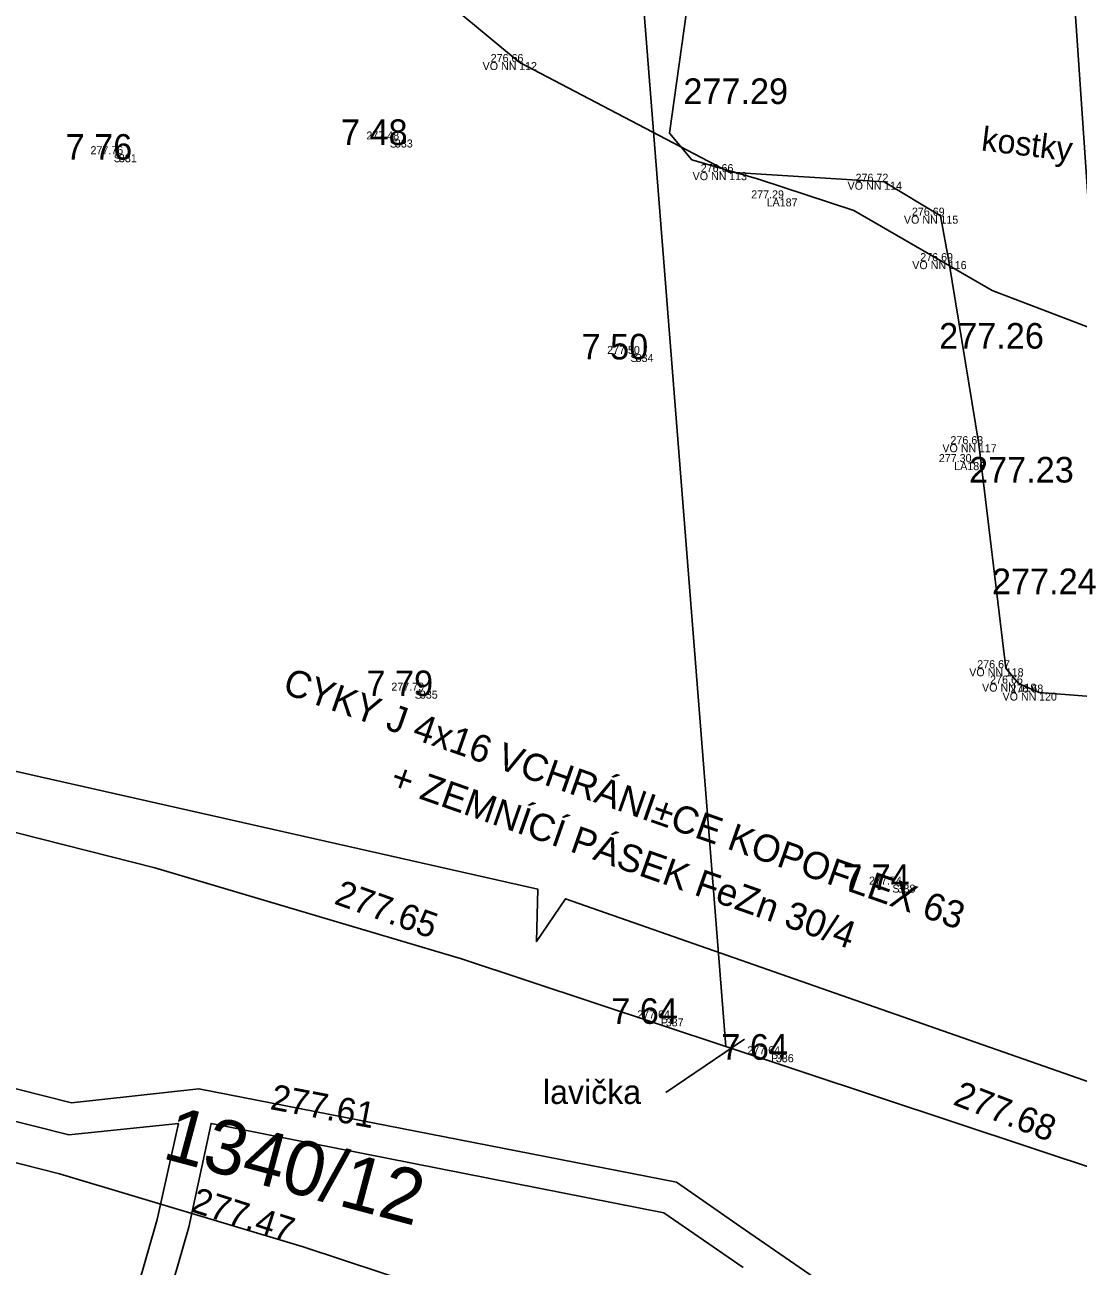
# Model space of a CAD drawing. Extents: x -601602 to -600882, y -1162594 to -1161950.
# Drawn here: x -601167.11 to -601150.66, y -1162089.58 to -1162070.19 of the extents above; entities that cross this region are included whole.
import ezdxf

# ---------------------------------------------------------------- set-up
doc = ezdxf.new("R2010")
doc.units = 0
for name, color, linetype in [('BODY', 7, 'Continuous'), ('BODY_CISLA', 7, 'Continuous'), ('BODY_KODY', 7, 'Continuous'), ('BODY_VYSKY_CELE', 7, 'Continuous'), ('G_TEXTY', 7, 'Continuous'), ('H_KOTY_VYSKOVE', 7, 'Continuous'), ('H_VYSKY_PREVZATE', 7, 'Continuous'), ('IS_EON_NN', 7, 'Continuous'), ('IS_VO', 7, 'Continuous'), ('IS_VO_AREAL', 7, 'Continuous'), ('KN_Hranice parcel', 7, 'Continuous'), ('KN_Parcelní čísla', 7, 'Continuous'), ('KN_Věcná břemena k části', 7, 'Continuous')]:
    doc.layers.add(name, color=color, linetype=linetype)

# ---------------------------------------------------------------- blocks, each defined once
blk = doc.blocks.new('POINT_DISPLAY')
blk.add_line((0, 0), (0, 0))

msp = doc.modelspace()

# ---------------------------------------------------------------- linework, layer by layer
at = {"layer": 'G_TEXTY'}
msp.add_line((-601157.098, -1162086.87), (-601155.868, -1162086.033), dxfattribs=at)
at = {"layer": 'IS_EON_NN'}
msp.add_lwpolyline([(-601156.45, -1162065.9), (-601156.46, -1162066.9), (-601156.74, -1162069.72), (-601157.04, -1162071.88), (-601156.69, -1162072.3), (-601155.65, -1162072.6), (-601154.16, -1162073.09), (-601152, -1162074.34), (-601150.35, -1162074.97), (-601148.58, -1162075.26), (-601146.13, -1162075.74), (-601143.03, -1162076.23), (-601141.99, -1162076.23)], dxfattribs=at)
at = {"layer": 'IS_VO'}
msp.add_lwpolyline([(-601221, -1162071.19), (-601220.94, -1162070.52), (-601220.15, -1162070.38), (-601205.25, -1162073.42), (-601205.07, -1162074.26), (-601204.715, -1162073.536), (-601188.58, -1162077.04), (-601188.36, -1162077.39), (-601188.09, -1162077.11), (-601183.9, -1162077.71), (-601173.92, -1162080.34), (-601173.63, -1162080.41), (-601159.1, -1162083.69), (-601159.12, -1162084.51), (-601158.666, -1162083.84), (-601145.3, -1162088.52)], dxfattribs=at)
at = {"layer": 'IS_VO_AREAL'}
msp.add_lwpolyline([(-601180.2, -1162059.82), (-601173.73, -1162060.12), (-601165.44, -1162058.83), (-601164.95, -1162058.87), (-601164.69, -1162059.39), (-601164.68, -1162062.58), (-601163.53, -1162066.21), (-601161.39, -1162069.11), (-601159.39, -1162070.77), (-601156.11, -1162072.49), (-601153.69, -1162072.64), (-601152.81, -1162073.17), (-601152.68, -1162073.88), (-601152.21, -1162076.74), (-601151.79, -1162080.24), (-601151.59, -1162080.48), (-601151.27, -1162080.62), (-601147.36, -1162080.92)], dxfattribs=at)
at = {"layer": 'KN_Hranice parcel'}
for p, q in [((-601149.45, -1162088.38), (-601151, -1162065.68)), ((-601156.16, -1162086.15), (-601149.45, -1162088.38))]:
    msp.add_line(p, q, dxfattribs=at)
for points in [[(-601158.55, -1162011.73), (-601158.56, -1162030.39), (-601158.54, -1162034.96), (-601158.53, -1162039.31), (-601158.48, -1162056.81), (-601158.01, -1162062.76), (-601156.16, -1162086.15)], [(-601156.16, -1162086.15), (-601160.29, -1162084.78), (-601165.08, -1162083.36), (-601173.19, -1162081.3), (-601181.3, -1162079.46), (-601222.59, -1162071.53)], [(-601189.82, -1162082.87), (-601182.15, -1162084.42), (-601174.31, -1162086.17), (-601166.57, -1162088.14), (-601162.76, -1162089.28), (-601132.72, -1162099.21)]]:
    msp.add_lwpolyline(points, dxfattribs=at)
at = {"layer": 'KN_Věcná břemena k části'}
for points in [[(-601153.16, -1162090.88), (-601155.94, -1162088.96), (-601156.93, -1162088.27), (-601164.39, -1162086.81), (-601166.38, -1162087.03), (-601178.19, -1162084.04), (-601179.35, -1162083.99), (-601180.98, -1162083.7), (-601187.61, -1162082.27), (-601194.69, -1162080.86)], [(-601194.77, -1162081.36), (-601187.71, -1162082.75), (-601181.08, -1162084.19), (-601179.41, -1162084.49), (-601178.27, -1162084.54), (-601166.42, -1162087.53), (-601164.71, -1162087.35), (-601165.04, -1162088.85), (-601165.84, -1162091.63)], [(-601165.36, -1162091.79), (-601164.55, -1162088.97), (-601164.2, -1162087.35), (-601157.13, -1162088.75), (-601155.89, -1162089.6)]]:
    msp.add_lwpolyline(points, dxfattribs=at)

# ---------------------------------------------------------------- block references
at = {"layer": 'BODY'}
for p in [(-601159.39, -1162070.77), (-601161.33, -1162071.98), (-601165.64, -1162072.21), (-601156.11, -1162072.49), (-601153.69, -1162072.64), (-601155.32, -1162072.9), (-601152.81, -1162073.17), (-601152.68, -1162073.88), (-601157.57, -1162075.33), (-601152.21, -1162076.74), (-601152.39, -1162077.02), (-601151.79, -1162080.24), (-601151.59, -1162080.48), (-601160.94, -1162080.59), (-601151.27, -1162080.62), (-601153.48, -1162083.62), (-601157.1, -1162085.71), (-601155.38, -1162086.27)]:
    msp.add_blockref('POINT_DISPLAY', p, dxfattribs=at)

# ---------------------------------------------------------------- texts
at = {"layer": 'BODY_CISLA'}
for s, p in [('112', (-601159.39, -1162070.895)), ('333', (-601161.33, -1162072.105)), ('331', (-601165.64, -1162072.335)), ('113', (-601156.11, -1162072.615)), ('114', (-601153.69, -1162072.765)), ('187', (-601155.32, -1162073.025)), ('115', (-601152.81, -1162073.295)), ('116', (-601152.68, -1162074.005)), ('334', (-601157.57, -1162075.455)), ('117', (-601152.21, -1162076.865)), ('186', (-601152.39, -1162077.145)), ('118', (-601151.79, -1162080.365)), ('119', (-601151.59, -1162080.605)), ('335', (-601160.94, -1162080.715)), ('120', (-601151.27, -1162080.745)), ('338', (-601153.48, -1162083.745)), ('337', (-601157.1, -1162085.835)), ('336', (-601155.38, -1162086.395))]:
    msp.add_text(s, height=0.125, dxfattribs=at).set_placement(p)
at = {"layer": 'BODY_KODY'}
for s, p in [('VO NN', (-601159.96, -1162070.895)), ('S', (-601161.411, -1162072.105)), ('S', (-601165.721, -1162072.335)), ('VO NN', (-601156.68, -1162072.615)), ('VO NN', (-601154.26, -1162072.765)), ('LA', (-601155.524, -1162073.025)), ('VO NN', (-601153.38, -1162073.295)), ('VO NN', (-601153.25, -1162074.005)), ('S', (-601157.651, -1162075.455)), ('VO NN', (-601152.78, -1162076.865)), ('LA', (-601152.594, -1162077.145)), ('VO NN', (-601152.36, -1162080.365)), ('VO NN', (-601152.16, -1162080.605)), ('S', (-601161.021, -1162080.715)), ('VO NN', (-601151.84, -1162080.745)), ('S', (-601153.561, -1162083.745)), ('P', (-601157.176, -1162085.835)), ('P', (-601155.456, -1162086.395))]:
    msp.add_text(s, height=0.125, dxfattribs=at).set_placement(p)
at = {"layer": 'BODY_VYSKY_CELE'}
for s, p in [('276.66 ', (-601159.834, -1162070.77)), ('277.48 ', (-601161.775, -1162071.98)), ('277.76 ', (-601166.084, -1162072.21)), ('276.66 ', (-601156.554, -1162072.49)), ('276.72 ', (-601154.135, -1162072.64)), ('277.29 ', (-601155.765, -1162072.9)), ('276.69 ', (-601153.255, -1162073.17)), ('276.69 ', (-601153.125, -1162073.88)), ('277.50 ', (-601158.015, -1162075.33)), ('276.63 ', (-601152.653, -1162076.74)), ('277.30 ', (-601152.835, -1162077.02)), ('276.67 ', (-601152.235, -1162080.24)), ('277.79 ', (-601161.385, -1162080.59)), ('276.66 ', (-601152.034, -1162080.48)), ('276.68 ', (-601151.715, -1162080.62)), ('277.74 ', (-601153.925, -1162083.62)), ('277.64 ', (-601157.545, -1162085.71)), ('277.64 ', (-601155.825, -1162086.27))]:
    msp.add_text(s, height=0.125, dxfattribs=at).set_placement(p)
at = {"layer": 'G_TEXTY'}
msp.add_text('kostky', height=0.375, rotation=353.0251, dxfattribs=at).set_placement((-601152.183, -1162072.15))
msp.add_text('lavička', height=0.375, dxfattribs=at).set_placement((-601159.017, -1162087.047))
at = {"layer": 'H_KOTY_VYSKOVE'}
for s, p in [(' 7 48', (-601162.321, -1162072.066)), (' 7 76', (-601166.622, -1162072.296)), (' 7 50', (-601158.563, -1162075.416)), (' 7 79', (-601161.922, -1162080.676)), (' 7 74', (-601154.48, -1162083.706)), (' 7 64', (-601158.1, -1162085.796)), (' 7 64', (-601156.38, -1162086.356))]:
    msp.add_text(s, height=0.4, dxfattribs=at).set_placement(p)
at = {"layer": 'H_VYSKY_PREVZATE'}
for s, p in [('277.29', (-601156.825, -1162071.426)), ('277.26', (-601152.83, -1162075.247)), ('277.23', (-601152.363, -1162077.339)), ('277.24', (-601152.005, -1162079.083))]:
    msp.add_text(s, height=0.4, dxfattribs=at).set_placement(p)
for s, rotation, p in [('277.65 ', 340.2205, (-601162.295, -1162083.914)), ('277.61 ', 349.3397, (-601163.292, -1162087.126)), ('277.68 ', 338.7872, (-601152.63, -1162087.05)), ('277.47 ', 342.0966, (-601164.536, -1162088.721))]:
    msp.add_text(s, height=0.4, rotation=rotation, dxfattribs=at).set_placement(p)
at = {"layer": 'IS_VO'}
for s, p in [('CYKY J 4x16 VCHRÁNI±CE KOPOFLEX 63', (-601163.103, -1162080.623)), ('+ ZEMNÍCÍ PÁSEK FeZn 30/4', (-601161.43, -1162082.109))]:
    msp.add_text(s, height=0.425, rotation=340.7035, dxfattribs=at).set_placement(p)
at = {"layer": 'KN_Parcelní čísla'}
msp.add_text('1340/12', height=0.85, rotation=345, dxfattribs=at).set_placement((-601164.983, -1162087.89))

doc.saveas('drawing.dxf')
